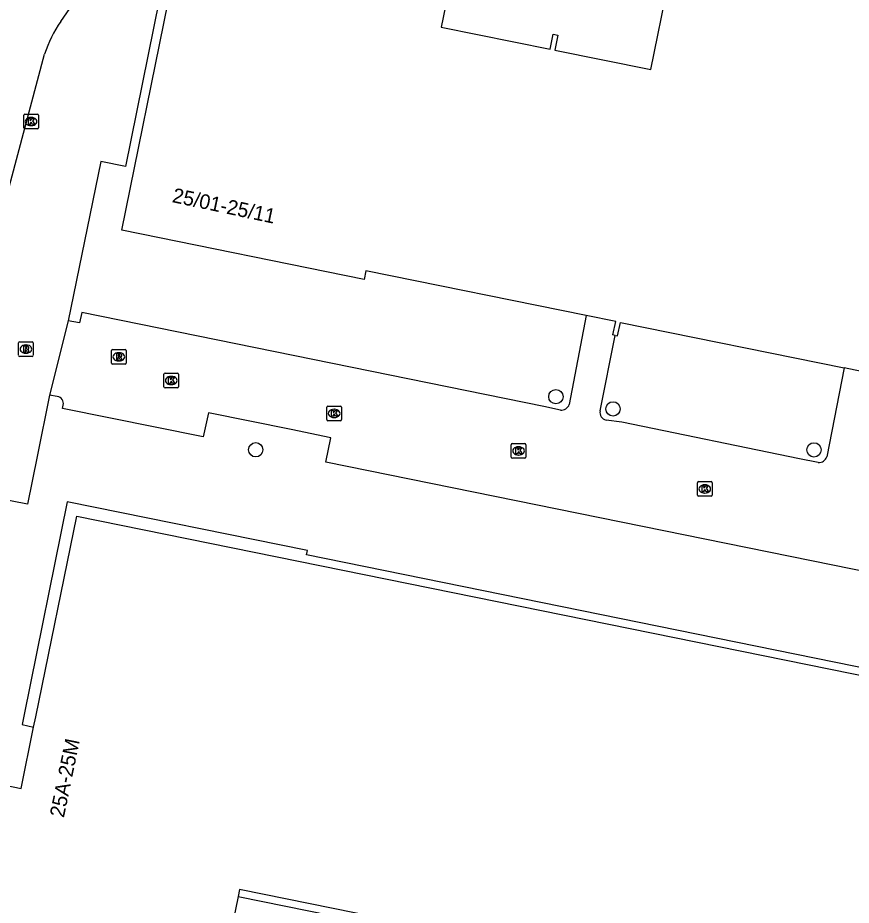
# Model space of a CAD drawing. Extents: x 157692 to 159670, y 381454 to 383289.
# Drawn here: x 158522.1 to 158579, y 381995.4 to 382056 of the extents above; entities that cross this region are included whole.
import ezdxf

# ---------------------------------------------------------------- set-up
doc = ezdxf.new("R2010")
doc.units = 0
for name, color, linetype in [('IMGEO_Boom', 7, 'Continuous'), ('IMGEO_Kolk', 7, 'Continuous'), ('IMGEO_Pand', 7, 'Continuous'), ('IMGEO_Pand_nummerreeks', 7, 'Continuous'), ('IMGEO_Pand_overbouw', 7, 'Continuous'), ('IMGEO_Rijbaan_lokaal_open', 7, 'Continuous'), ('IMGEO_Rioolput', 7, 'Continuous')]:
    doc.layers.add(name, color=color, linetype=linetype)

msp = doc.modelspace()

# ---------------------------------------------------------------- linework, layer by layer
at = {"layer": 'IMGEO_Boom'}
for centre in [(158558.85, 382030.103), (158562.749, 382029.269), (158538.353, 382026.481), (158576.471, 382026.474)]:
    msp.add_circle(centre, 0.489, dxfattribs=at)
at = {"layer": 'IMGEO_Kolk'}
for p, q in [((158522.515, 382048.459), (158522.515, 382049.311)), ((158522.59, 382049.385), (158523.442, 382049.385)), ((158523.003, 382049.165), (158523.028, 382049.165)), ((158523.516, 382049.311), (158523.516, 382048.459)), ((158523.026, 382048.605), (158523.001, 382048.605)), ((158523.442, 382048.385), (158522.59, 382048.385)), ((158532.087, 382030.781), (158532.087, 382031.633)), ((158532.162, 382031.707), (158533.014, 382031.707)), ((158533.088, 382031.633), (158533.088, 382030.781)), ((158532.575, 382031.487), (158532.6, 382031.487)), ((158533.014, 382030.707), (158532.162, 382030.707)), ((158532.598, 382030.927), (158532.573, 382030.927)), ((158543.209, 382028.538), (158543.209, 382029.39)), ((158543.284, 382029.464), (158544.136, 382029.464)), ((158543.697, 382029.244), (158543.722, 382029.244)), ((158544.21, 382029.39), (158544.21, 382028.538)), ((158543.72, 382028.684), (158543.695, 382028.684)), ((158544.136, 382028.464), (158543.284, 382028.464)), ((158555.801, 382025.977), (158555.801, 382026.829)), ((158555.876, 382026.903), (158556.728, 382026.903)), ((158556.802, 382026.829), (158556.802, 382025.977)), ((158556.312, 382026.123), (158556.287, 382026.123)), ((158556.289, 382026.683), (158556.314, 382026.683)), ((158556.728, 382025.903), (158555.876, 382025.903)), ((158568.589, 382024.308), (158569.441, 382024.308)), ((158568.514, 382023.382), (158568.514, 382024.234)), ((158569.002, 382024.088), (158569.027, 382024.088)), ((158569.515, 382024.234), (158569.515, 382023.382)), ((158569.441, 382023.308), (158568.589, 382023.308)), ((158569.025, 382023.528), (158569, 382023.528))]:
    msp.add_line(p, q, dxfattribs=at)
for points in [[(158522.515, 382048.459), (158522.515, 382049.311)], [(158522.59, 382049.385), (158523.442, 382049.385)], [(158523.516, 382049.311), (158523.516, 382048.459)], [(158522.836, 382049.085), (158522.959, 382049.085), (158522.959, 382048.934), (158523.089, 382049.085), (158523.253, 382049.085), (158523.107, 382048.934), (158523.26, 382048.685), (158523.108, 382048.685), (158523.023, 382048.849), (158522.959, 382048.782), (158522.959, 382048.685), (158522.836, 382048.685), (158522.836, 382049.085)], [(158523.442, 382048.385), (158522.59, 382048.385)], [(158532.087, 382030.781), (158532.087, 382031.633)], [(158532.162, 382031.707), (158533.014, 382031.707)], [(158533.088, 382031.633), (158533.088, 382030.781)], [(158532.408, 382031.407), (158532.531, 382031.407), (158532.531, 382031.256), (158532.661, 382031.407), (158532.825, 382031.407), (158532.679, 382031.256), (158532.832, 382031.007), (158532.68, 382031.007), (158532.595, 382031.171), (158532.531, 382031.104), (158532.531, 382031.007), (158532.408, 382031.007), (158532.408, 382031.407)], [(158533.014, 382030.707), (158532.162, 382030.707)], [(158543.209, 382028.538), (158543.209, 382029.39)], [(158543.284, 382029.464), (158544.136, 382029.464)], [(158543.53, 382029.164), (158543.653, 382029.164), (158543.653, 382029.013), (158543.783, 382029.164), (158543.947, 382029.164), (158543.801, 382029.013), (158543.954, 382028.764), (158543.802, 382028.764), (158543.717, 382028.928), (158543.653, 382028.861), (158543.653, 382028.764), (158543.53, 382028.764), (158543.53, 382029.164)], [(158544.21, 382029.39), (158544.21, 382028.538)], [(158544.136, 382028.464), (158543.284, 382028.464)], [(158555.801, 382025.977), (158555.801, 382026.829)], [(158555.876, 382026.903), (158556.728, 382026.903)], [(158556.802, 382026.829), (158556.802, 382025.977)], [(158556.122, 382026.603), (158556.245, 382026.603), (158556.245, 382026.452), (158556.375, 382026.603), (158556.539, 382026.603), (158556.393, 382026.452), (158556.546, 382026.203), (158556.394, 382026.203), (158556.309, 382026.367), (158556.245, 382026.3), (158556.245, 382026.203), (158556.122, 382026.203), (158556.122, 382026.603)], [(158556.728, 382025.903), (158555.876, 382025.903)], [(158568.589, 382024.308), (158569.441, 382024.308)], [(158568.514, 382023.382), (158568.514, 382024.234)], [(158568.835, 382024.008), (158568.958, 382024.008), (158568.958, 382023.857), (158569.088, 382024.008), (158569.252, 382024.008), (158569.106, 382023.857), (158569.259, 382023.608), (158569.107, 382023.608), (158569.022, 382023.772), (158568.958, 382023.705), (158568.958, 382023.608), (158568.835, 382023.608), (158568.835, 382024.008)], [(158569.515, 382024.234), (158569.515, 382023.382)], [(158569.441, 382023.308), (158568.589, 382023.308)]]:
    msp.add_lwpolyline(points, dxfattribs=at)
for centre, start, end in [((158522.592, 382049.309), 91.55205, 178.44795), ((158522.592, 382049.309), 91.55205, 178.44795), ((158523.44, 382049.309), 1.55205, 88.44795), ((158523.44, 382049.309), 1.55205, 88.44795), ((158522.592, 382048.461), 181.55205, 268.44795), ((158522.592, 382048.461), 181.55205, 268.44795), ((158523.44, 382048.461), 271.55205, 358.44795), ((158523.44, 382048.461), 271.55205, 358.44795), ((158532.164, 382031.631), 91.55205, 178.44795), ((158532.164, 382031.631), 91.55205, 178.44795), ((158533.012, 382031.631), 1.55205, 88.44795), ((158533.012, 382031.631), 1.55205, 88.44795), ((158532.164, 382030.783), 181.55205, 268.44795), ((158532.164, 382030.783), 181.55205, 268.44795), ((158533.012, 382030.783), 271.55205, 358.44795), ((158533.012, 382030.783), 271.55205, 358.44795), ((158543.286, 382029.388), 91.55205, 178.44795), ((158543.286, 382029.388), 91.55205, 178.44795), ((158544.134, 382029.388), 1.55205, 88.44795), ((158544.134, 382029.388), 1.55205, 88.44795), ((158543.286, 382028.54), 181.55205, 268.44795), ((158543.286, 382028.54), 181.55205, 268.44795), ((158544.134, 382028.54), 271.55205, 358.44795), ((158544.134, 382028.54), 271.55205, 358.44795), ((158555.878, 382026.827), 91.55205, 178.44795), ((158555.878, 382026.827), 91.55205, 178.44795), ((158556.726, 382026.827), 1.55205, 88.44795), ((158556.726, 382026.827), 1.55205, 88.44795), ((158555.878, 382025.979), 181.55205, 268.44795), ((158555.878, 382025.979), 181.55205, 268.44795), ((158556.726, 382025.979), 271.55205, 358.44795), ((158556.726, 382025.979), 271.55205, 358.44795), ((158568.591, 382024.232), 91.55205, 178.44795), ((158568.591, 382024.232), 91.55205, 178.44795), ((158569.439, 382024.232), 1.55205, 88.44795), ((158569.439, 382024.232), 1.55205, 88.44795), ((158568.591, 382023.384), 181.55205, 268.44795), ((158568.591, 382023.384), 181.55205, 268.44795), ((158569.439, 382023.384), 271.55205, 358.44795), ((158569.439, 382023.384), 271.55205, 358.44795)]:
    msp.add_arc(centre, 0.0765, start, end, dxfattribs=at)
for centre, major_axis, ratio, start_param, end_param in [((158523.002, 382048.885), (-0.387, 0.002), 0.722429, 4.712389, 7.853982), ((158523.027, 382048.885), (-0.39, 0.002), 0.717154, 1.570796, 4.712389), ((158532.574, 382031.207), (-0.387, 0.002), 0.722429, 4.712389, 7.853982), ((158532.599, 382031.207), (-0.39, 0.002), 0.717154, 1.570796, 4.712389), ((158543.696, 382028.964), (-0.387, 0.002), 0.722429, 4.712389, 7.853982), ((158543.721, 382028.964), (-0.39, 0.002), 0.717154, 1.570796, 4.712389), ((158556.288, 382026.403), (-0.387, 0.002), 0.722429, 4.712389, 7.853982), ((158556.313, 382026.403), (-0.39, 0.002), 0.717154, 1.570796, 4.712389), ((158569.001, 382023.808), (-0.387, 0.002), 0.722429, 4.712389, 7.853982), ((158569.026, 382023.808), (-0.39, 0.002), 0.717154, 1.570796, 4.712389)]:
    msp.add_ellipse(centre, major_axis=major_axis, ratio=ratio, start_param=start_param, end_param=end_param, dxfattribs=at)
at = {"layer": 'IMGEO_Pand'}
for points in [[(158552.242, 382061.302), (158551.018, 382055.337), (158558.446, 382053.835), (158558.653, 382054.854), (158558.986, 382054.787), (158558.779, 382053.768), (158565.334, 382052.437), (158566.542, 382058.382)], [(158560.91, 382035.64), (158545.877, 382038.706), (158545.753, 382038.099), (158529.205, 382041.46), (158532.366, 382057.038)], [(158562.891, 382034.292), (158562.746, 382034.323), (158562.937, 382035.227), (158560.91, 382035.64)], [(158562.891, 382034.292), (158563.059, 382034.257), (158563.253, 382035.176), (158578.536, 382032.067)], [(158580.511, 382030.734), (158580.39, 382030.76), (158580.581, 382031.651), (158578.536, 382032.067)], [(158628.896, 381977.861), (158551.508, 381993.562), (158546.79, 381994.52), (158537.238, 381996.458), (158537.162, 381995.98), (158535.731, 381988.998), (158519.182, 381992.341), (158521.352, 382003.003), (158519.908, 382003.291), (158520.013, 382003.834), (158522.34, 382003.369), (158523.175, 382007.551), (158523.336, 382008.252), (158526.141, 382021.958), (158633.426, 382000.171), (158628.896, 381977.861)]]:
    msp.add_lwpolyline(points, dxfattribs=at)
at = {"layer": 'IMGEO_Pand_overbouw'}
msp.add_lwpolyline([(158537.162, 381995.98), (158546.696, 381994.043), (158551.412, 381993.084), (158629.29, 381977.261), (158634.018, 382000.555), (158541.821, 382019.31), (158541.878, 382019.607), (158525.478, 382022.916), (158522.548, 382008.404), (158522.41, 382007.723), (158523.175, 382007.551), (158523.336, 382008.252), (158526.141, 382021.958), (158633.426, 382000.171), (158628.896, 381977.861), (158551.508, 381993.562), (158546.79, 381994.52), (158537.238, 381996.458)], close=True, dxfattribs=at)
at = {"layer": 'IMGEO_Rijbaan_lokaal_open'}
for points in [[(158525.034, 382055.722), (158526.735, 382058.178), (158526.89, 382058.147), (158531.761, 382057.161), (158529.467, 382045.826), (158527.765, 382046.147), (158525.552, 382035.293)], [(158519.613, 382037.428), (158520.266, 382039.789), (158523.937, 382053.475)], [(158559.163, 382029.191), (158558.034, 382029.439), (158526.484, 382035.842), (158526.323, 382035.147), (158525.552, 382035.293)], [(158525.552, 382035.293), (158524.275, 382030.209)], [(158560.91, 382035.64), (158559.763, 382029.579)], [(158561.86, 382029.135), (158562.891, 382034.292)], [(158578.536, 382032.067), (158577.339, 382026.009)], [(158524.275, 382030.209), (158523.422, 382026.011), (158522.762, 382022.762), (158520.771, 382023.159), (158520.515, 382023.224)], [(158524.803, 382030.122), (158524.275, 382030.209)], [(158641.091, 382005.9), (158641.056, 382005.738), (158543.145, 382025.64), (158543.48, 382027.287), (158540.782, 382027.856), (158535.136, 382029.001), (158534.769, 382027.354), (158525.158, 382029.297), (158525.205, 382029.531)], [(158576.76, 382025.611), (158575.476, 382025.865), (158563.362, 382028.365), (158562.274, 382028.501)]]:
    msp.add_lwpolyline(points, dxfattribs=at)
for centre, radius, start, end in [((158532.278, 382050.794), 8.761, 145.77349, 162.18265), ((158524.737, 382029.645), 0.482, 346.34736, 82.09996), ((158559.216, 382029.766), 0.578, 264.68933, 341.08947), ((158562.426, 382029.053), 0.572, 171.72824, 254.56058), ((158576.817, 382026.148), 0.54, 263.9437, 345.06494)]:
    msp.add_arc(centre, radius, start, end, dxfattribs=at)
at = {"layer": 'IMGEO_Rioolput'}
for p, q in [((158522.164, 382032.927), (158522.164, 382033.779)), ((158522.239, 382033.853), (158523.091, 382033.853)), ((158522.652, 382033.633), (158522.677, 382033.633)), ((158523.165, 382033.779), (158523.165, 382032.927)), ((158523.091, 382032.853), (158522.239, 382032.853)), ((158522.675, 382033.073), (158522.65, 382033.073)), ((158528.506, 382032.4), (158528.506, 382033.252)), ((158528.581, 382033.326), (158529.433, 382033.326)), ((158528.994, 382033.106), (158529.019, 382033.106)), ((158529.507, 382033.252), (158529.507, 382032.4)), ((158529.433, 382032.326), (158528.581, 382032.326)), ((158529.017, 382032.546), (158528.992, 382032.546))]:
    msp.add_line(p, q, dxfattribs=at)
for points in [[(158522.164, 382032.927), (158522.164, 382033.779)], [(158522.239, 382033.853), (158523.091, 382033.853)], [(158522.753, 382033.551), (158522.501, 382033.553), (158522.501, 382033.153)], [(158522.679, 382033.472), (158522.625, 382033.472), (158522.625, 382033.391)], [(158522.625, 382033.391), (158522.677, 382033.391)], [(158523.165, 382033.779), (158523.165, 382032.927)], [(158523.091, 382032.853), (158522.239, 382032.853)], [(158522.501, 382033.153), (158522.625, 382033.153), (158522.625, 382033.315), (158522.636, 382033.315)], [(158522.683, 382033.286), (158522.754, 382033.153), (158522.894, 382033.153), (158522.829, 382033.279)], [(158528.506, 382032.4), (158528.506, 382033.252)], [(158528.581, 382033.326), (158529.433, 382033.326)], [(158529.095, 382033.024), (158528.843, 382033.026), (158528.843, 382032.626)], [(158528.843, 382032.626), (158528.967, 382032.626), (158528.967, 382032.788), (158528.978, 382032.788)], [(158529.021, 382032.945), (158528.967, 382032.945), (158528.967, 382032.864)], [(158528.967, 382032.864), (158529.019, 382032.864)], [(158529.507, 382033.252), (158529.507, 382032.4)], [(158529.433, 382032.326), (158528.581, 382032.326)], [(158529.025, 382032.759), (158529.096, 382032.626), (158529.236, 382032.626), (158529.171, 382032.752)]]:
    msp.add_lwpolyline(points, dxfattribs=at)
for centre, radius, start, end in [((158522.241, 382033.777), 0.0765, 91.55205, 178.44795), ((158522.241, 382033.777), 0.0765, 91.55205, 178.44795), ((158522.661, 382033.58), 0.19, 274.7715, 282.96867), ((158522.685, 382033.376), 0.0964, 77.00612, 93.18647), ((158522.699, 382033.433), 0.0378, 276.66336, 79.67722), ((158522.752, 382033.441), 0.109, 350.36119, 89.41601), ((158522.75, 382033.441), 0.112, 277.58423, 350.98172), ((158523.089, 382033.777), 0.0765, 1.55205, 88.44795), ((158523.089, 382033.777), 0.0765, 1.55205, 88.44795), ((158522.241, 382032.929), 0.0765, 181.55205, 268.44795), ((158522.241, 382032.929), 0.0765, 181.55205, 268.44795), ((158522.635, 382033.262), 0.0533, 26.02933, 88.69889), ((158522.734, 382033.226), 0.108, 29.51342, 73.79051), ((158523.089, 382032.929), 0.0765, 271.55205, 358.44795), ((158523.089, 382032.929), 0.0765, 271.55205, 358.44795), ((158528.583, 382033.25), 0.0765, 91.55205, 178.44795), ((158528.583, 382033.25), 0.0765, 91.55205, 178.44795), ((158528.977, 382032.735), 0.0533, 26.02933, 88.69889), ((158529.003, 382033.053), 0.19, 274.7715, 282.96867), ((158529.027, 382032.849), 0.0964, 77.00612, 93.18647), ((158529.041, 382032.906), 0.0378, 276.66336, 79.67722), ((158529.094, 382032.914), 0.109, 350.36119, 89.41601), ((158529.092, 382032.914), 0.112, 277.58423, 350.98172), ((158529.076, 382032.699), 0.108, 29.51342, 73.79051), ((158529.431, 382033.25), 0.0765, 1.55205, 88.44795), ((158529.431, 382033.25), 0.0765, 1.55205, 88.44795), ((158528.583, 382032.402), 0.0765, 181.55205, 268.44795), ((158528.583, 382032.402), 0.0765, 181.55205, 268.44795), ((158529.431, 382032.402), 0.0765, 271.55205, 358.44795), ((158529.431, 382032.402), 0.0765, 271.55205, 358.44795)]:
    msp.add_arc(centre, radius, start, end, dxfattribs=at)
for centre, major_axis, ratio, start_param, end_param in [((158522.651, 382033.353), (-0.387, 0.002), 0.722429, 4.712389, 7.853982), ((158522.676, 382033.353), (-0.39, 0.002), 0.717154, 1.570796, 4.712389), ((158528.993, 382032.826), (-0.387, 0.002), 0.722429, 4.712389, 7.853982), ((158529.018, 382032.826), (-0.39, 0.002), 0.717154, 1.570796, 4.712389)]:
    msp.add_ellipse(centre, major_axis=major_axis, ratio=ratio, start_param=start_param, end_param=end_param, dxfattribs=at)

# ---------------------------------------------------------------- texts
at = {"layer": 'IMGEO_Pand_nummerreeks'}
for s, rotation, p in [('25/01-25/11', 348.01853, (158532.596, 382043.392)), ('25A-25M', 78.34084, (158525.251, 382001.327))]:
    msp.add_text(s, height=1, rotation=rotation, dxfattribs=at).set_placement(p)

doc.saveas('drawing.dxf')
